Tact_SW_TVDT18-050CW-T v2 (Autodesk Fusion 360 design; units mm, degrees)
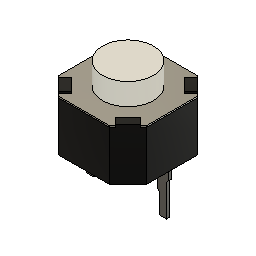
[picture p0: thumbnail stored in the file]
sketch "スケッチ" plane through (0, 0, 0) normal (0, 1, 0) x axis (1, 0, 0)
  line L1 (3, 0) -> (0, 0)
  line L2 (3, -3) -> (3, 0)
  line L3 (0, -3) -> (3, -3)
  line L4 (0, 0) -> (0, -3)
  line L5 (-3, -3) -> (3, -3)
  line L6 (-3, 3) -> (-3, -3)
  line L7 (3, 3) -> (-3, 3)
  line L8 (3, -3) -> (3, 3)
  line L9 (-1.75, -3) -> (0, -3)
  line L10 (-1.75, 3) -> (-1.75, -3)
  line L11 (0, 3) -> (-1.75, 3)
  line L12 (0, -3) -> (0, 3)
  line L13 (1.75, -3) -> (-1.75, -3)
  line L14 (1.75, 3) -> (1.75, -3)
  line L15 (-1.75, 3) -> (1.75, 3)
  line L16 (-1.75, -3) -> (-1.75, 3)
  line L17 (3, 0) -> (-3, 0)
  line L18 (3, -1.75) -> (3, 0)
  line L19 (-3, -1.75) -> (3, -1.75)
  line L20 (-3, 0) -> (-3, -1.75)
  line L21 (3, -1.75) -> (-3, -1.75)
  line L22 (3, 1.75) -> (3, -1.75)
  line L23 (-3, 1.75) -> (3, 1.75)
  line L24 (-3, -1.75) -> (-3, 1.75)
  line L25 (-1.75, 3) -> (-3, 1.75)
  line L26 (3, 1.75) -> (1.75, 3)
  line L27 (1.75, -3) -> (3, -1.75)
  line L28 (-3, -1.75) -> (-1.75, -3)
  line L29 (3, -3) -> (-3, 3)
  line L30 (-3, -3) -> (3, 3)
  line L31 (2.5757, -3.4243) -> (-3.4243, 2.5757)
  line L32 (3.4243, -2.5757) -> (-2.5757, 3.4243)
  line L33 (-3.4243, -2.5757) -> (2.5757, 3.4243)
  line L34 (-2.5757, -3.4243) -> (3.4243, 2.5757)
  line L35 (-1.3257, 2.5757) -> (-2.5757, 1.3257)
  line L36 (2.5757, 1.3257) -> (1.3257, 2.5757)
  line L37 (-2.5757, -1.3257) -> (-1.3257, -2.5757)
  line L38 (1.3257, -2.5757) -> (2.5757, -1.3257)
  line L39 (-2.5, 0) -> (0, 0)
  line L40 (-2.5, -0.1) -> (-2.5, 0)
  line L41 (0, -0.1) -> (-2.5, -0.1)
  line L42 (0, 0) -> (0, -0.1)
  line L43 (-2.9, 0) -> (-2.5, 0)
  line L44 (-2.9, 0.1) -> (-2.9, 0)
  line L45 (-2.5, 0.1) -> (-2.9, 0.1)
  line L46 (-2.5, 0) -> (-2.5, 0.1)
  line L47 (-2.1, 0.1) -> (-2.9, 0.1)
  line L48 (-2.1, -0.1) -> (-2.1, 0.1)
  line L49 (-2.9, -0.1) -> (-2.1, -0.1)
  line L50 (-2.9, 0.1) -> (-2.9, -0.1)
  line L51 (-2.75, 0.1) -> (-2.5, 0.1)
  line L52 (-2.75, -0.1) -> (-2.75, 0.1)
  line L53 (-2.5, -0.1) -> (-2.75, -0.1)
  line L54 (-2.5, 0.1) -> (-2.5, -0.1)
  line L55 (-2.25, 0.1) -> (-2.75, 0.1)
  line L56 (-2.25, -0.1) -> (-2.25, 0.1)
  line L57 (-2.75, -0.1) -> (-2.25, -0.1)
  line L58 (-2.75, 0.1) -> (-2.75, -0.1)
  line L59 (2.1, -0.1) -> (2.1, 0.1)
  line L60 (2.1, 0.1) -> (2.9, 0.1)
  line L61 (2.25, -0.1) -> (2.25, 0.1)
  line L62 (2.9, -0.1) -> (2.1, -0.1)
  line L63 (2.5, -0.1) -> (2.5, 0)
  line L64 (2.5, 0.1) -> (2.5, -0.1)
  line L65 (2.75, 0.1) -> (2.75, -0.1)
  line L66 (2.9, 0.1) -> (2.9, -0.1)
  circle C1 centre (0, 0) radius 1.75
  point P1 (0, 0)
  point P2 (0, 0)
  point P15 (-3, 0)
  point P22 (0, 0)
  point P39 (0, 0)
  point P40 (-2.5, 0)
  point P61 (2.5, 0)
  point P41 (-2.5, -0.1)
  point P62 (2.5, -0.1)
  point P44 (-2.9, 0.1)
  point P57 (2.9, 0.1)
  point P45 (-2.5, 0.1)
  point P64 (2.5, 0.1)
  point P46 (-2.1, 0.1)
  point P55 (2.1, 0.1)
  point P47 (-2.1, -0.1)
  point P56 (2.1, -0.1)
  point P48 (-2.9, -0.1)
  point P60 (2.9, -0.1)
  point P49 (-2.75, 0.1)
  point P66 (2.75, 0.1)
  point P51 (-2.5, -0.1)
  point P63 (2.5, -0.1)
  point P52 (-2.25, 0.1)
  point P58 (2.25, 0.1)
  point P53 (-2.25, -0.1)
  point P59 (2.25, -0.1)
  point P54 (-2.75, -0.1)
  point P65 (2.75, -0.1)
  point P3 (3, 0)
  point P5 (0, -3)
  point P4 (3, -3)
  point P6 (-3, -3)
  point P8 (3, 3)
  point P9 (-1.75, -3)
  point P11 (0, 3)
  point P12 (1.75, -3)
  point P14 (-1.75, 3)
  point P16 (3, 0)
  point P18 (-3, -1.75)
  point P19 (3, -1.75)
  point P21 (-3, 1.75)
  point P42 (0, -0.1)
  point P43 (-2.9, 0)
  horizontal L1
  vertical L2
  horizontal L3
  vertical L4
  coincident P1 P2
  horizontal L5
  vertical L6
  horizontal L7
  vertical L8
  horizontal L9
  vertical L10
  horizontal L11
  vertical L12
  horizontal L13
  vertical L14
  horizontal L15
  vertical L16
  horizontal L17
  vertical L18
  horizontal L19
  vertical L20
  midpoint L6 P15
  horizontal L21
  vertical L22
  horizontal L23
  vertical L24
  coincident P1 P22
  tangent L14 C1
  horizontal L39
  vertical L40
  horizontal L41
  vertical L42
  coincident P1 P39
  horizontal L43
  vertical L44
  horizontal L45
  vertical L46
  horizontal L47
  vertical L48
  horizontal L49
  vertical L50
  horizontal L51
  vertical L52
  horizontal L53
  vertical L54
  horizontal L55
  vertical L56
  horizontal L57
  vertical L58
  symmetric L12 P40 P61
  symmetric L12 P41 P62
  symmetric L12 P44 P57
  symmetric L12 P45 P64
  symmetric L12 P46 P55
  symmetric L12 P47 P56
  symmetric L12 P48 P60
  symmetric L12 P49 P66
  symmetric L12 P51 P63
  symmetric L12 P52 P58
  symmetric L12 P53 P59
  symmetric L12 P54 P65
  dimension "d1" distance P2 P3 = 3
  dimension "d2" distance P2 P5 = 3
  dimension "d3" distance P4 P6 = 6
  dimension "d4" distance P4 P8 = 6
  dimension "d5" distance P5 P9 = 1.75 (= "( 3.5 / 2 ) * 1 mm")
  dimension "d6" distance P5 P11 = 6
  dimension "d7" distance P9 P12 = 3.5
  dimension "d8" distance P9 P14 = 6
  dimension "d9" distance P15 P16 = 6
  dimension "d10" distance P15 P18 = 1.75 (= "( 3.5 / 2 ) * 1 mm")
  dimension "d11" distance P18 P19 = 6
  dimension "d12" distance P18 P21 = 3.5
  dimension "d19" = 0.6
  dimension "d20" = -0.6
  dimension "d21" = 0.6
  dimension "d22" = -0.6
  dimension "d23" = 0.6
  dimension "d24" = 0.6
  dimension "d25" = 0.6
  dimension "d26" = 0.6
  dimension "d35" distance P39 P40 = 2.5
  dimension "d36" distance P39 P42 = 0.1
  dimension "d37" distance P40 P43 = 0.4
  dimension "d38" distance P40 P45 = 0.1
  dimension "d39" distance P44 P46 = 0.8
  dimension "d40" distance P44 P48 = 0.2
  dimension "d41" distance P45 P49 = 0.25
  dimension "d42" distance P45 P51 = 0.2
  dimension "d43" distance P49 P52 = 0.5
  dimension "d44" distance P49 P54 = 0.2
extrude "押し出し1" new body sketch "スケッチ" profile of L1 L4 L12 L17 C1 along normal blind 5 bodies "SW"
extrude "押し出し2" cut sketch "スケッチ" profile of L1 L4 L12 L17 C1 along normal blind 3.5
extrude "押し出し3" new body sketch "スケッチ" profile of L1 L2 L3 L4 L5 L6 L7 L8 L9 L10 L11 L12 L13 L14 L15 L16 L17 L18 L19 L20 L21 L22 L23 L24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 along normal blind 3.5 bodies "TopPlate"
extrude "押し出し4" cut sketch "スケッチ" profile of L10 L14 L16 L19 L21 L23 L25 L26 L27 L28 L29 L30 L31 L32 L33 L34 L35 L36 L37 L38 along normal blind 3.6
extrude "押し出し5" new body sketch "スケッチ" profile of L10 L14 L16 L19 L21 L23 L25 L26 L27 L28 L29 L30 L31 L32 L33 L34 L35 L36 L37 L38 along normal blind 3.6 bodies "Body"
extrude "押し出し6" cut sketch "スケッチ" profile of L1 L2 L3 L4 L5 L6 L7 L8 L9 L10 L11 L12 L13 L14 L15 L16 L17 L18 L19 L20 L21 L22 L23 L24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 along normal blind 3.4
extrude "押し出し7" new body sketch "スケッチ" profile of L1 L2 L3 L4 L5 L6 L7 L8 L9 L10 L11 L12 L13 L14 L15 L16 L17 L18 L19 L20 L21 L22 L23 L24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 along normal blind 3.4
combine "結合"
extrude "押し出し8" new body sketch "スケッチ" profile of L1 L17 L39 L40 L41 L43 L44 L45 L46 L47 L48 L49 L50 L51 L52 L53 L54 L55 L56 L57 L58 L59 L60 L61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 against normal blind 0.8 bodies "Pin1", "Pin2"
extrude "押し出し9" add sketch "スケッチ" profile of L1 L17 L39 L40 L41 L43 L45 L46 L47 L48 L49 L51 L52 L53 L54 L55 L56 L57 L58 L59 L60 L61 L62 L63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 against normal blind 1.6
extrude "押し出し10" add sketch "スケッチ" profile of L1 L17 L39 L40 L41 L43 L45 L46 L47 L49 L51 L52 L53 L54 L55 L56 L57 L58 L60 L61 L62 L63 L64 L65 against normal blind 3
chamfer "面取り1" distance 0.15
chamfer "面取り2" distance 0.15
chamfer "面取り3" distance 0.15
chamfer "面取り4" distance 0.15
named bodies: "SW", "TopPlate", "Body", "Pin1", "Pin2"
